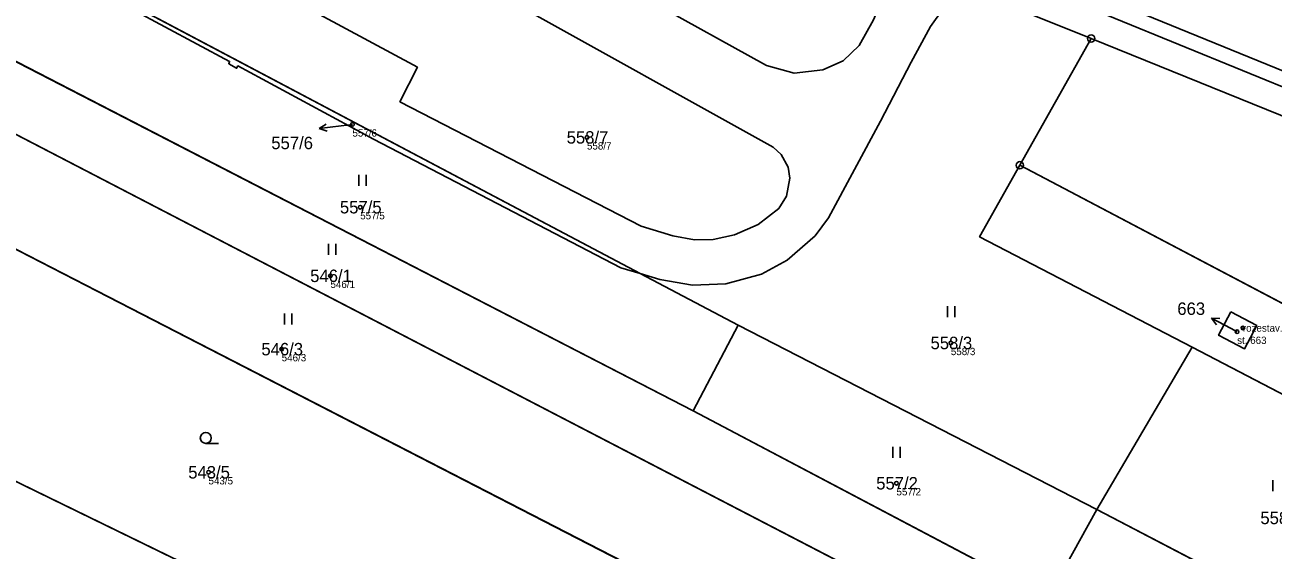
# Model space of a CAD drawing. Extents: x -761891 to -756141, y -1178507 to -1171885.
# Drawn here: x -759488.5 to -759318.1, y -1174313.5 to -1174241.7 of the extents above; entities that cross this region are included whole.
import ezdxf

# ---------------------------------------------------------------- set-up
doc = ezdxf.new("R2010")
doc.units = 0
for name, color, linetype in [('Definiční body', 7, 'Continuous'), ('Hranice parcel', 7, 'Continuous'), ('Parcelní čísla', 7, 'Continuous'), ('Polygon budovy', 7, 'Continuous'), ('Polygon parcely', 7, 'Continuous'), ('Pop  PČ popisy', 7, 'Continuous'), ('Vnitřní kresba', 7, 'Continuous'), ('Značky bodu BP', 7, 'Continuous'), ('Značky budov', 7, 'Continuous'), ('Značky kultur', 7, 'Continuous')]:
    doc.layers.add(name, color=color, linetype=linetype)

msp = doc.modelspace()

# ---------------------------------------------------------------- linework, layer by layer
at = {"layer": 'Definiční body'}
for centre in [(-759443.77, -1174255.3), (-759411.75, -1174257.07), (-759442.71, -1174266.61), (-759446.77, -1174275.99), (-759322.98, -1174283.64), (-759322.2, -1174283.12), (-759453.43, -1174286.01), (-759362.07, -1174285.17), (-759463.42, -1174302.84), (-759369.49, -1174304.34)]:
    msp.add_circle(centre, 0.25, dxfattribs=at)
at = {"layer": 'Hranice parcel'}
for p, q in [((-759404.47, -1174275.67), (-759487.6, -1174231.65)), ((-759397.25, -1174294.42), (-759514.35, -1174233.98)), ((-759518.39, -1174241.78), (-759369.71, -1174319)), ((-759352.66, -1174260.88), (-759342.92, -1174243.56)), ((-759395.81, -1174320.74), (-759525.68, -1174253.84)), ((-759269.47, -1174304.68), (-759352.66, -1174260.88)), ((-759391.12, -1174282.74), (-759404.47, -1174275.67)), ((-759424.99, -1174335.66), (-759542.29, -1174278.44)), ((-759391.12, -1174282.74), (-759397.25, -1174294.42)), ((-759342.14, -1174307.92), (-759391.12, -1174282.74)), ((-759329.14, -1174285.76), (-759342.14, -1174307.92)), ((-759276.21, -1174313.35), (-759329.14, -1174285.76)), ((-759348.85, -1174319.99), (-759397.25, -1174294.42)), ((-759346.66, -1174316.06), (-759342.14, -1174307.92)), ((-759292.3, -1174333.94), (-759342.14, -1174307.92))]:
    msp.add_line(p, q, dxfattribs=at)
for points in [[(-759476.11, -1174186.16), (-759472.65, -1174186.76), (-759456.18, -1174193.35), (-759427.71, -1174204.87), (-759357.02, -1174233.66), (-759278.8, -1174265.71), (-759254.21, -1174280.96), (-759233.15, -1174304.27), (-759219.81, -1174328.11)], [(-759370.37, -1174232.54), (-759370.54, -1174234.88), (-759371.43, -1174238.23), (-759372.65, -1174241.02), (-759374.57, -1174244.53), (-759376.79, -1174246.59), (-759379.53, -1174247.83), (-759383.46, -1174248.31), (-759387.26, -1174247.26), (-759403.03, -1174238.5), (-759425.36, -1174226.04), (-759440.7, -1174217.45), (-759454.45, -1174211.35), (-759465.59, -1174205.24), (-759469.56, -1174203.14), (-759474.19, -1174201.22), (-759478.21, -1174200.59), (-759481.52, -1174200.84), (-759484.62, -1174201.65), (-759484.83, -1174201.35), (-759485.68, -1174201.76), (-759485.57, -1174202.11), (-759488.17, -1174203.59), (-759491.14, -1174206.34)], [(-759404.47, -1174275.67), (-759407.12, -1174274.88), (-759440.89, -1174257.32), (-759459.41, -1174247.31), (-759459.58, -1174247.63), (-759460.66, -1174247.01), (-759460.54, -1174246.68), (-759482.61, -1174234.79), (-759487.03, -1174232.35), (-759487.6, -1174231.65)], [(-759421.89, -1174238.63), (-759386.32, -1174258.42), (-759385.25, -1174259.43), (-759384.27, -1174261.16), (-759384.07, -1174262.64), (-759384.52, -1174265.11), (-759385.57, -1174266.8), (-759388.37, -1174268.96), (-759391.6, -1174270.38), (-759394.53, -1174271.02), (-759397.09, -1174271.05), (-759400.02, -1174270.53), (-759404.37, -1174269.2), (-759437.3, -1174252.2), (-759434.91, -1174247.48), (-759454.95, -1174236.61)], [(-759360.05, -1174236.64), (-759360.6, -1174237.03), (-759363.1, -1174239.49), (-759364.86, -1174241.92), (-759367.5, -1174246.77), (-759371.69, -1174254.84), (-759378.78, -1174268.08), (-759380.61, -1174270.51), (-759384.41, -1174273.84), (-759387.9, -1174275.78), (-759392.81, -1174277.08), (-759397.33, -1174277.27), (-759401.81, -1174276.47), (-759404.47, -1174275.67)], [(-759342.92, -1174243.56), (-759358.25, -1174237.36), (-759360.05, -1174236.64)], [(-759251.77, -1174288.32), (-759256.44, -1174283.54), (-759280.18, -1174268.96), (-759342.92, -1174243.56)], [(-759329.14, -1174285.76), (-759358.15, -1174270.64), (-759352.66, -1174260.88)], [(-759323.84, -1174280.93), (-759325.52, -1174284.12), (-759321.98, -1174285.98), (-759320.31, -1174282.8), (-759323.84, -1174280.93)]]:
    msp.add_lwpolyline(points, dxfattribs=at)
at = {"layer": 'Polygon budovy'}
msp.add_lwpolyline([(-759323.84, -1174280.93), (-759325.52, -1174284.12), (-759321.98, -1174285.98), (-759320.31, -1174282.8)], close=True, dxfattribs=at)
at = {"layer": 'Polygon parcely'}
for points in [[(-759301.25, -1174241.62), (-759352.82, -1174221.03), (-759422.72, -1174192.32), (-759463.05, -1174175.24), (-759469.3, -1174171.9), (-759471.45, -1174176.4), (-759475.07, -1174183.99), (-759476.11, -1174186.16), (-759472.65, -1174186.76), (-759456.18, -1174193.35), (-759427.71, -1174204.87), (-759357.02, -1174233.66), (-759278.8, -1174265.71)], [(-759487.6, -1174231.65), (-759404.47, -1174275.67), (-759401.81, -1174276.47), (-759397.33, -1174277.27), (-759392.81, -1174277.08), (-759387.9, -1174275.78), (-759384.41, -1174273.84), (-759380.61, -1174270.51), (-759378.78, -1174268.08), (-759371.69, -1174254.84), (-759367.5, -1174246.77), (-759364.86, -1174241.92), (-759363.1, -1174239.49)], [(-759421.89, -1174238.63), (-759386.32, -1174258.42), (-759385.25, -1174259.43), (-759384.27, -1174261.16), (-759384.07, -1174262.64), (-759384.52, -1174265.11), (-759385.57, -1174266.8), (-759388.37, -1174268.96), (-759391.6, -1174270.38), (-759394.53, -1174271.02), (-759397.09, -1174271.05), (-759400.02, -1174270.53), (-759404.37, -1174269.2), (-759437.3, -1174252.2), (-759434.91, -1174247.48), (-759454.95, -1174236.61)], [(-759454.95, -1174236.61), (-759434.91, -1174247.48), (-759437.3, -1174252.2), (-759404.37, -1174269.2), (-759400.02, -1174270.53), (-759397.09, -1174271.05), (-759394.53, -1174271.02), (-759391.6, -1174270.38), (-759388.37, -1174268.96), (-759385.57, -1174266.8), (-759384.52, -1174265.11), (-759384.07, -1174262.64), (-759384.27, -1174261.16), (-759385.25, -1174259.43), (-759386.32, -1174258.42), (-759421.89, -1174238.63)], [(-759372.65, -1174241.02), (-759374.57, -1174244.53), (-759376.79, -1174246.59), (-759379.53, -1174247.83), (-759383.46, -1174248.31), (-759387.26, -1174247.26), (-759403.03, -1174238.5)], [(-759403.03, -1174238.5), (-759387.26, -1174247.26), (-759383.46, -1174248.31), (-759379.53, -1174247.83), (-759376.79, -1174246.59), (-759374.57, -1174244.53), (-759372.65, -1174241.02)]]:
    msp.add_lwpolyline(points, dxfattribs=at)
for points in [[(-759232.79, -1174309.18), (-759220.92, -1174329.84), (-759219.81, -1174328.11), (-759233.15, -1174304.27), (-759254.21, -1174280.96), (-759278.8, -1174265.71), (-759357.02, -1174233.66), (-759427.71, -1174204.87), (-759456.18, -1174193.35), (-759472.65, -1174186.76), (-759476.11, -1174186.16), (-759476.58, -1174187.14), (-759478.82, -1174191.78), (-759461.66, -1174196.95), (-759429.39, -1174209.09), (-759370.37, -1174232.54), (-759360.05, -1174236.64), (-759358.25, -1174237.36), (-759342.92, -1174243.56), (-759280.18, -1174268.96), (-759256.44, -1174283.54), (-759251.77, -1174288.32), (-759246.79, -1174293.4), (-759234.83, -1174305.62)], [(-759440.89, -1174257.32), (-759459.41, -1174247.31), (-759459.58, -1174247.63), (-759460.66, -1174247.01), (-759460.54, -1174246.68), (-759482.61, -1174234.79), (-759487.03, -1174232.35), (-759487.6, -1174231.65), (-759507.43, -1174221.15), (-759514.35, -1174233.98), (-759397.25, -1174294.42), (-759391.12, -1174282.74), (-759404.47, -1174275.67), (-759407.12, -1174274.88)], [(-759487.6, -1174231.65), (-759487.03, -1174232.35), (-759482.61, -1174234.79), (-759460.54, -1174246.68), (-759460.66, -1174247.01), (-759459.58, -1174247.63), (-759459.41, -1174247.31), (-759440.89, -1174257.32), (-759407.12, -1174274.88), (-759404.47, -1174275.67)], [(-759336.1, -1174326.69), (-759348.85, -1174319.99), (-759397.25, -1174294.42), (-759514.35, -1174233.98), (-759518.39, -1174241.78), (-759369.71, -1174319), (-759339.74, -1174334.55)], [(-759397.33, -1174277.27), (-759401.81, -1174276.47), (-759404.47, -1174275.67), (-759391.12, -1174282.74), (-759342.14, -1174307.92), (-759329.14, -1174285.76), (-759358.15, -1174270.64), (-759352.66, -1174260.88), (-759342.92, -1174243.56), (-759358.25, -1174237.36), (-759360.05, -1174236.64), (-759360.6, -1174237.03), (-759363.1, -1174239.49), (-759364.86, -1174241.92), (-759367.5, -1174246.77), (-759371.69, -1174254.84), (-759378.78, -1174268.08), (-759380.61, -1174270.51), (-759384.41, -1174273.84), (-759387.9, -1174275.78), (-759392.81, -1174277.08)], [(-759376.18, -1174330.85), (-759369.71, -1174319), (-759518.39, -1174241.78), (-759525.68, -1174253.84), (-759395.81, -1174320.74)], [(-759269.47, -1174304.68), (-759251.77, -1174288.32), (-759256.44, -1174283.54), (-759280.18, -1174268.96), (-759342.92, -1174243.56), (-759352.66, -1174260.88)], [(-759541.44, -1174276.12), (-759542.29, -1174278.44), (-759424.99, -1174335.66), (-759383.51, -1174355.89), (-759408.09, -1174343.48), (-759395.81, -1174320.74), (-759525.68, -1174253.84), (-759526.82, -1174255.46)], [(-759352.66, -1174260.88), (-759358.15, -1174270.64), (-759329.14, -1174285.76), (-759276.21, -1174313.35), (-759274.63, -1174313.97), (-759269.47, -1174304.68)], [(-759502.04, -1174324.42), (-759485.58, -1174332.63), (-759481.97, -1174334.42), (-759481.45, -1174334.68), (-759477.7, -1174336.56), (-759474.81, -1174338), (-759474, -1174338.4), (-759449.86, -1174350.5), (-759446.36, -1174352.11), (-759443.04, -1174353.67), (-759438.33, -1174355.93), (-759437.25, -1174356.51), (-759430.69, -1174345.35), (-759424.99, -1174335.66), (-759542.29, -1174278.44), (-759547.2, -1174288.12), (-759552.83, -1174299.21)], [(-759323.84, -1174280.93), (-759325.52, -1174284.12), (-759321.98, -1174285.98), (-759320.31, -1174282.8)], [(-759323.84, -1174280.93), (-759320.31, -1174282.8), (-759321.98, -1174285.98), (-759325.52, -1174284.12)], [(-759348.85, -1174319.99), (-759346.66, -1174316.06), (-759342.14, -1174307.92), (-759391.12, -1174282.74), (-759397.25, -1174294.42)], [(-759342.14, -1174307.92), (-759292.3, -1174333.94), (-759289.81, -1174329.55), (-759283.17, -1174317.85), (-759278.65, -1174320.54), (-759276.21, -1174313.35), (-759329.14, -1174285.76)], [(-759292.31, -1174350.08), (-759285.47, -1174337.74), (-759292.3, -1174333.94), (-759342.14, -1174307.92), (-759346.66, -1174316.06), (-759328.96, -1174325.37), (-759331.14, -1174329.3), (-759315.38, -1174337.6)]]:
    msp.add_lwpolyline(points, close=True, dxfattribs=at)
at = {"layer": 'Pop  PČ popisy'}
for p, q in [((-759448.3, -1174255.87), (-759447.37, -1174255.25)), ((-759443.77, -1174255.3), (-759445.32, -1174255.5)), ((-759445.32, -1174255.5), (-759448.3, -1174255.87)), ((-759448.3, -1174255.87), (-759447.24, -1174256.24)), ((-759323.82, -1174283.2), (-759326.47, -1174281.79)), ((-759326.47, -1174281.79), (-759325.35, -1174281.82)), ((-759326.47, -1174281.79), (-759325.82, -1174282.7)), ((-759322.98, -1174283.64), (-759323.82, -1174283.2))]:
    msp.add_line(p, q, dxfattribs=at)
at = {"layer": 'Vnitřní kresba'}
msp.add_line((-759278.01, -1174263.86), (-759353.3, -1174233.02), dxfattribs=at)
at = {"layer": 'Značky bodu BP'}
for centre, radius in [((-759342.92, -1174243.56), 0.5), ((-759342.92, -1174243.56), 0.0303), ((-759352.66, -1174260.88), 0.5), ((-759352.66, -1174260.88), 0.0303)]:
    msp.add_circle(centre, radius, dxfattribs=at)
at = {"layer": 'Značky budov'}
msp.add_circle((-759322.21, -1174283.12), 0.175, dxfattribs=at)
at = {"layer": 'Značky kultur'}
for p, q in [((-759442.91, -1174263.68), (-759442.91, -1174262.18)), ((-759441.91, -1174263.68), (-759441.91, -1174262.18)), ((-759447.04, -1174273.13), (-759447.04, -1174271.63)), ((-759446.04, -1174273.13), (-759446.04, -1174271.63)), ((-759362.54, -1174281.64), (-759362.54, -1174280.14)), ((-759361.54, -1174281.64), (-759361.54, -1174280.14)), ((-759453.04, -1174282.66), (-759453.04, -1174281.16)), ((-759452.04, -1174282.66), (-759452.04, -1174281.16)), ((-759463.79, -1174298.89), (-759462.04, -1174298.89)), ((-759370, -1174300.87), (-759370, -1174299.37)), ((-759369, -1174300.87), (-759369, -1174299.37)), ((-759318.12, -1174305.42), (-759318.12, -1174303.92))]:
    msp.add_line(p, q, dxfattribs=at)
msp.add_circle((-759463.79, -1174298.14), 0.75, dxfattribs=at)

# ---------------------------------------------------------------- texts
at = {"layer": 'Definiční body'}
for s, p in [('557/6', (-759443.77, -1174256.96)), ('558/7', (-759411.75, -1174258.73)), ('557/5', (-759442.71, -1174268.27)), ('546/1', (-759446.77, -1174277.65)), ('rozestav.', (-759322.2, -1174283.62)), ('st. 663', (-759322.98, -1174285.3)), ('558/3', (-759362.07, -1174286.83)), ('546/3', (-759453.43, -1174287.67)), ('543/5', (-759463.42, -1174304.5)), ('557/2', (-759369.49, -1174306))]:
    msp.add_text(s, height=1, dxfattribs=at).set_placement(p)
at = {"layer": 'Parcelní čísla'}
for s, p in [('557/6', (-759454.85, -1174258.68)), ('558/7', (-759414.52, -1174257.92)), ('557/5', (-759445.48, -1174267.46)), ('546/1', (-759449.54, -1174276.84)), ('663', (-759331.15, -1174281.33)), ('558/3', (-759364.84, -1174286.02)), ('546/3', (-759456.2, -1174286.86)), ('543/5', (-759466.19, -1174303.69)), ('557/2', (-759372.26, -1174305.19)), ('558/1', (-759319.81, -1174309.93))]:
    msp.add_text(s, height=1.7, dxfattribs=at).set_placement(p)

doc.saveas('drawing.dxf')
